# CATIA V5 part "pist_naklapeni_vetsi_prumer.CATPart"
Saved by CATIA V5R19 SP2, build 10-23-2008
Part number: Part1.1
Bounding box of the stored display mesh (mm): x -44.968 to 44.968, y -42.705 to 422.295, z -54.812 to 54.812
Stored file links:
  C:\Users\Martin\Desktop\9.semestr\Projekt-diplomka\3D model\pist_naklapeni_vetsi_prumer.CATPart
  C:\Program Files\Dassault Systemes\B19\intel_a\startup\materials\Catalog.CATMaterial
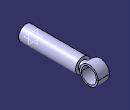
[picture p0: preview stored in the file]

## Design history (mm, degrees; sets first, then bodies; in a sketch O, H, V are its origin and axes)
Body1 (main body)
  Sketch1 on yz-plane, origin (0, 0, 0), H (0, 1, 0), V (0, 0, 1)
    axis line L1 (371.4804, 0) -> (-60.2057, 0)
    point P1 (371.4804, 0)
    point P3 (297.2948, 45)
    line L2 (297.2948, 45) -> (-42.7052, 45)
    line L3 (-42.7052, 45) -> (-42.7052, 35)
    line L4 (-42.7052, 35) -> (287.2948, 35)
    line L5 (287.2948, 35) -> (287.2948, 0)
    point P7 (287.2948, 0)
    line L6 (297.2948, 45) -> (297.2948, 0)
    point P8 (297.2948, 0)
    "Radius" L4 L1 = 35
    "Radius" L1 L2 = 45
    distance L5 L3 = 330
    distance L3 P3 = 340
    coincidence: P1 H, P7 L1, P8 L1
    horizontal: L1 H, L2 H, L4 H
    vertical: L3 V, L5 V, L6 V
  Shaft1: profile Sketch1, axis Sketch1.L1, angle 360
  Sketch2 on yz-plane, origin (0, 0, 0), H (0, 1, 0), V (0, 0, 1)
    circle A1 centre (367.2948, 0) radius 55
    point P1 (367.2948, 0)
    circle A2 centre (367.2948, 0) radius 45
    reference projected line E1 (297.2948, -45) -> (297.2948, 45) from edge [face of Shaft1 from Sketch1.L6 | face of Shaft1 from Sketch1.L2]
    radius A1 = 55
    radius A2 = 45
    distance P1 E1 = 70
    coincidence: P1 H
  Pad1: profile Sketch2, direction (1, 0, 0), length 34, mirrored extent
  Sketch3 on face of Shaft1 from Sketch1.L6, origin (0, 297.2948, 0), H (-1, 0, 0), V (0, 0, 1)
    circle A1 centre (0, 0) radius 27.5
    radius A1 = 27.5
  Pad2: profile Sketch3, direction (0, 1, 0), up to the existing solid (limit type 2)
